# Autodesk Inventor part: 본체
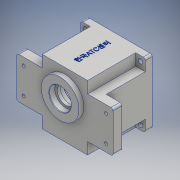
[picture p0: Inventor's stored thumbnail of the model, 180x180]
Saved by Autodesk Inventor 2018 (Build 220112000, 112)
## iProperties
Created: 2020-07
Part Number: 본체
Material: 알루미늄 6061
Document SubType Name: Modeling
Designer: Admin
Density: 2.7 g/cm^3
Appearance: 알루미늄 - 평지
Mass: 876.486 g
Surface Area: 793.573 cm^2
Volume: 324.624 cm^3
Author: Admin
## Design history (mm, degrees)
sketch "스케치1"
  geometry: L1 (47, -47)-(-47, -47); L2 (-47, -47)-(-47, 47); L3 (-47, 47)-(47, 47); L4 (47, 47)-(47, -47); L5 (47, -47)-(-47, 47); L6 (-47, -47)-(47, 47); L7 (70, -30)-(-70, -30); L8 (-70, -30)-(-70, 30); L9 (-70, 30)-(70, 30); L10 (70, 30)-(70, -30); L11 (70, -30)-(-70, 30); L12 (-70, -30)-(70, 30); 1 further point
  constraints: 24 end point, 4 midpoint, 4 parallel, 2 horizontal, 2 perpendicular
  dimensions: "d0" = 94 distance of L2.end L3.end; "d1" = 94 distance of L1.end L2.end; "d2" = 140 distance of L8.end L9.end; "d3" = 60 distance of L7.end L8.end
extrude "돌출1" new body sketch "스케치1" stored distance "d4" = 80; taper "d5" = 0 deg
sketch "스케치2"
  geometry: L1 (94, 0)-(94, -80) reference; L2 (0, 0)-(94, 0) reference; L3 (0, 0)-(0, -80) reference; L4 (94, -80)-(0, -80) reference; L5 (0, -80)-(0, 0) reference; L6 (-23, 0)-(0, 0) reference; L7 (-23, 0)-(-23, -80) reference; L8 (0, -80)-(-23, -80) reference; L9 (94, 0)-(94, -80) reference; L10 (117, -80)-(94, -80) reference; L11 (117, 0)-(117, -80) reference; L12 (94, 0)-(117, 0) reference; L13 (94, 0)-(117, 0); L14 (117, 0)-(117, -67); L15 (117, -67)-(94, -67); L16 (94, -67)-(94, 0); L17 (0, 0)-(-23, 0) reference; L18 (0, -80)-(0, 0) reference; L19 (-23, 0)-(0, 0); L20 (0, 0)-(0, -67); L21 (0, -67)-(-23, -67); L22 (-23, -67)-(-23, 0); 1 further point
  constraints: 16 end point, 4 parallel, 3 point on line, 2 horizontal, 2 perpendicular
  dimensions: "d6" = 13 distance between parallel lines of L10 L15
extrude "돌출2" cut sketch "스케치2" extent not by distance; stored distance "d7" = 80; taper "d8" = 0 deg
sketch "스케치3"
  geometry: L1 (47, 30)-(47, 47) reference; L2 (47, 47)-(-47, 47) reference; L3 (-47, 47)-(-47, 30) reference; L4 (-47, 30)-(-70, 30) reference; L5 (-70, 30)-(-70, -30) reference; L6 (-70, -30)-(-47, -30) reference; L7 (-47, -30)-(-47, -47) reference; L8 (-47, -47)-(47, -47) reference; L9 (47, -47)-(47, -30) reference; L10 (47, -30)-(70, -30) reference; L11 (70, -30)-(70, 30) reference; L12 (70, 30)-(47, 30) reference; L13 (47, 47)-(-47, 47) reference; L14 (-47, 47)-(-33, 47); L15 (-33, 47)-(-33, 30); L16 (-33, 30)-(-47, 30); L17 (-47, 30)-(-47, 47); L18 (47, 47)-(33, 47); L19 (33, 47)-(33, 30); L20 (33, 30)-(47, 30); L21 (47, 30)-(47, 47); L22 (0, -65.8)-(0, 65.8) reference; L23 (-98, 0)-(98, 0) reference; L24 (-47, -47)-(47, -47) reference; L25 (-47, -30)-(-33, -30); L26 (-33, -30)-(-33, -47); L27 (-33, -47)-(-47, -47); L28 (-47, -47)-(-47, -30); L29 (47, -30)-(33, -30); L30 (33, -30)-(33, -47); L31 (33, -47)-(47, -47); L32 (47, -47)-(47, -30); 1 further point
  constraints: 32 end point, 8 parallel, 4 horizontal, 4 perpendicular, 3 symmetric about line, 2 point on line
  dimensions: "d9" = 66 distance between parallel lines of L19 L15
extrude "돌출3" cut sketch "스케치3" distance "d10" = 70; taper "d11" = 0 deg
sketch "스케치4"
  geometry: L1 (-98, 0)-(98, 0) reference; L2 (0, -65.8)-(0, 65.8) reference; 5 further points
  constraints: 4 symmetric about line
  dimensions: "d12" = 80 distance of point (-40, 40) point (40, 40); "d13" = 80 distance of point (40, -40) point (40, 40)
hole "구멍1" sketch "스케치4" at (-40, 40), (40, 40), (-40, -40), (40, -40) diameter "d14" = 7; stored, may be unused: countersink angle "d18" = 90 deg, drill point angle "d20" = 118 deg; dims "d15" = 6, "d16" = 4, "d17" = 2, "d19" = 8
sketch "스케치5"
  geometry: L1 (-33, -30)-(-33, -47) reference; L2 (-33, -47)-(33, -47) reference; L3 (33, -47)-(33, -30) reference; L4 (33, -30)-(70, -30) reference; L5 (70, -30)-(70, 30) reference; L6 (70, 30)-(33, 30) reference; L7 (33, 30)-(33, 47) reference; L8 (33, 47)-(-33, 47) reference; L9 (-33, 47)-(-33, 30) reference; L10 (-33, 30)-(-70, 30) reference; L11 (-70, 30)-(-70, -30) reference; L12 (-70, -30)-(-33, -30) reference; C1 r 27.5 at (0, 11); 1 further point
  constraints: 1 centre point, 1 vertical alignment
  dimensions: "d21" = 55 diameter of C1; "d22" = 11 distance of point (0, 0) C1.centre
extrude "돌출4" join sketch "스케치5" distance "d23" = 7; taper "d24" = 0 deg
sketch "스케치6"
  geometry: L1 (-80, 60)-(-80, 77) reference; L2 (-80, 77)-(-14, 77) reference; L3 (-14, 77)-(-14, 60) reference; L4 (-14, 60)-(23, 60) reference; L5 (23, 60)-(23, 0) reference; L6 (23, 0)-(-14, 0) reference; L7 (-14, 0)-(-14, -17) reference; L8 (-14, -17)-(-80, -17) reference; L9 (-80, -17)-(-80, 0) reference; L10 (-80, 0)-(-117, 0) reference; L11 (-117, 0)-(-117, 60) reference; L12 (-117, 60)-(-80, 60) reference; L13 (-145, 30)-(51, 30) reference; L14 (-47, 95.8)-(-47, -35.8) reference; C1 r 27.5 at (-47, 19) reference; 5 further points
  constraints: 3 symmetric about line
  dimensions: "d25" = 120 distance of point (-107, 11) point (13, 11); "d26" = 38 distance of point (-107, 49) point (-107, 11)
hole "구멍2" sketch "스케치6" at (13, 11), (13, 49), (-107, 11), (-107, 49) diameter "d27" = 4.5; stored, may be unused: countersink angle "d31" = 90 deg, drill point angle "d33" = 118 deg; dims "d28" = 6, "d29" = 10, "d30" = 5, "d32" = 8
sketch "스케치7"
  geometry: L1 (-47, 38.5)-(-47, -16.5) reference; L2 (-40, -16.5)-(-40, 38.5) reference; L3 (-40, 47)-(-40, 30) reference; L4 (30, 47)-(-40, 47) reference; L5 (30, 47)-(30, 30) reference; L6 (-40, 30)-(30, 30) reference; L7 (-64.4, 0)-(57.4, 0) reference; L8 (-47, 38.5)-(-47, -16.5) reference; L9 (-47, 27)-(-38.7, 27); L10 (-38.7, 27)-(-38.7, 11); L11 (-38.7, 11)-(-47, 11); L12 (-47, 11)-(-47, 27); L13 (-38.7, 11)-(-34, 11); L14 (-34, 11)-(-34, 23.5); L15 (-34, 23.5)-(-38.7, 23.5); L16 (-38.7, 23.5)-(-38.7, 11); L17 (-34, 11)-(-24, 11); L18 (-24, 11)-(-24, 28.5); L19 (-24, 28.5)-(-34, 28.5); L20 (-34, 28.5)-(-34, 11); 1 further point
  constraints: 24 end point, 6 parallel, 3 horizontal, 3 perpendicular, 1 point on line
  dimensions: "d34" = 16 distance of L9.end L10.end; "d35" = 12.5 distance between parallel lines of L13 L15; "d36" = 17.5 distance of L17.end L18.end; "d37" = 11 distance between parallel lines of L7 L17; "d38" = 8.3 distance of L9.start L9.end; "d40" = 10 distance of L18.end L19.end; "d73" = 23 distance between parallel lines of L18 L1
revolve "회전1" sketch "스케치7" stored, may be unused: angle "d41" = 90 deg
sketch "스케치8"
  geometry: L1 (-24, 28.5)-(-24, -6.5) reference; L2 (-64.4, 0)-(57.4, 0) reference; L3 (-34, -20)-(-31, -20); L4 (-31, -20)-(-31, -29.5); L5 (-31, -29.5)-(-34, -29.5); L6 (-34, -29.5)-(-34, -20); L7 (-31, -20)-(-24, -20); L8 (-24, -20)-(-24, -31); L9 (-24, -31)-(-31, -31); L10 (-31, -31)-(-31, -20); 1 further point
  constraints: 16 end point, 4 parallel, 2 horizontal, 2 perpendicular, 1 point on line
  dimensions: "d42" = 11 distance of L7.end L8.end; "d43" = 9.5 distance of L5.end L3.start; "d44" = 20 distance between parallel lines of L7 L2; "d45" = 3 distance of L4.end L5.end; "d46" = 7 distance of L8.end L9.end
revolve "회전2" sketch "스케치8" stored, may be unused: angle "d47" = 90 deg
sketch "스케치9"
  geometry: C1 r 43 at (0, 0); 1 further point
  constraints: 1 centre point, 1 coincident
  dimensions: "d48" = 86 diameter of C1
extrude "돌출5" cut sketch "스케치9" distance "d49" = 9; taper "d50" = 0 deg
sketch "스케치10"
  geometry: C1 r 40 at (0, 0); 1 further point
  constraints: 1 centre point, 1 coincident
  dimensions: "d51" = 80 diameter of C1
extrude "돌출6" cut sketch "스케치10" distance "d52" = 55; taper "d53" = 0 deg
sketch "스케치11"
  geometry: C1 r 11 at (0, 20) reference; C2 r 17.5 at (0, -11) reference; C3 r 40 at (0, 0) reference; C4 r 40 at (0, 0); A1 r 21 centre (0, -11) between (-8.978, 7.984) and (8.978, 7.984); A2 r 15 centre (0, 20) between (8.978, 7.984) and (-8.978, 7.984); 1 further point
  constraints: 4 point on circle, 3 centre point, 3 coincident
  dimensions: "d54" = 42 diameter of A1; "d55" = 30 diameter of A2; "d56" = 80 diameter of C4
extrude "돌출7" cut sketch "스케치11" distance "d57" = 7; taper "d58" = 0 deg
sketch "스케치12" dims "d60" = 72
  geometry: L1 (-98, 0)-(98, 0) reference; L2 (0, 65.8)-(0, -65.8) reference; L3 (39.799, -4)-(36, -4); L4 (39.799, 4)-(36, 4); L5 (-39.799, -4)-(-36, -4); L6 (-39.799, 4)-(-36, 4); A1 r 21 centre (0, -11) between (-8.978, 7.984) and (8.978, 7.984) reference; A2 r 15 centre (0, 20) between (8.978, 7.984) and (-8.978, 7.984) reference; A3 r 40 centre (0, 0) between (39.799, 4) and (39.799, -4) reference; A4 r 4 centre (36, 0) between (36, 4) and (36, -4); A5 r 40 centre (0, 0) between (39.799, -4) and (39.799, 4); A6 r 4 centre (-36, 0) between (-36, -4) and (-36, 4); A7 r 40 centre (0, 0) between (-39.799, 4) and (-39.799, -4); 2 further points
  constraints: 10 point on circle, 8 end point, 5 symmetric about line, 4 centre point, 2 coincident, 2 horizontal, 2 tangent, 1 horizontal alignment, 1 point on line, 4 other
  dimensions: "d59" = 8 diameter of A4
extrude "돌출8" join sketch "스케치12" stored distance "d61" = 7; taper "d62" = 0 deg
sketch "스케치13"
  geometry: L1 (-39.799, -4)-(-36, -4) reference; L2 (-36, 4)-(-39.799, 4) reference; L3 (36, 4)-(39.799, 4) reference; L4 (39.799, -4)-(36, -4) reference; C1 r 43 at (0, 0) reference; A1 r 40 centre (0, 0) between (-39.799, -4) and (39.799, -4) reference; A2 r 4 centre (-36, 0) between (-36, -4) and (-36, 4) reference; A3 r 40 centre (0, 0) between (39.799, 4) and (-39.799, 4) reference; A4 r 4 centre (36, 0) between (36, 4) and (36, -4) reference; 3 further points
  constraints: 2 coincident
hole "구멍3" sketch "스케치13" at (36, 0), (-36, 0) diameter "d63" = 3.242; stored, may be unused: countersink angle "d67" = 90 deg, drill point angle "d69" = 118 deg; dims "d64" = 7, "d65" = 10, "d66" = 5, "d68" = 9
chamfer "모따기1" distance "d70" = 0.8; stored, may be unused: second distance "d71" = 2, angle "d72" = 30 deg
chamfer "모따기2" distance "d74" = 1; stored, may be unused: second distance "d75" = 2, angle "d76" = 30 deg
fillet "모깎기1" dims "d77" = 3
sketch "스케치14"
  geometry: L1 (77, 80)-(77, 70) reference; L2 (-11, 80)-(77, 80) reference; L3 (-11, 70)-(-11, 80) reference; L4 (-11, 70)-(0, 70) reference; L5 (0, 70)-(0, 0) reference; L6 (66, 0)-(0, 0) reference; L7 (66, 0)-(66, 70) reference; L8 (66, 70)-(77, 70) reference; 2 further points
  constraints: 1 coincident, 1 other
  dimensions: "d78" = 40 distance from line of L2 point (33, 40)
feature "엠보싱1" sketch "스케치14" dims "d79" = 0.5, "d80" = 0
node "솔리드1"
node "투영된 루프1"
node "투영된 루프2"
node "투영된 루프3"
node "투영된 루프4"
node "투영된 루프5"
node "투영된 루프6"
node "투영된 루프7"
node "투영된 루프8"
node "투영된 루프9"
node "투영된 루프10"
node "투영된 루프11"
node "투영된 루프12"
